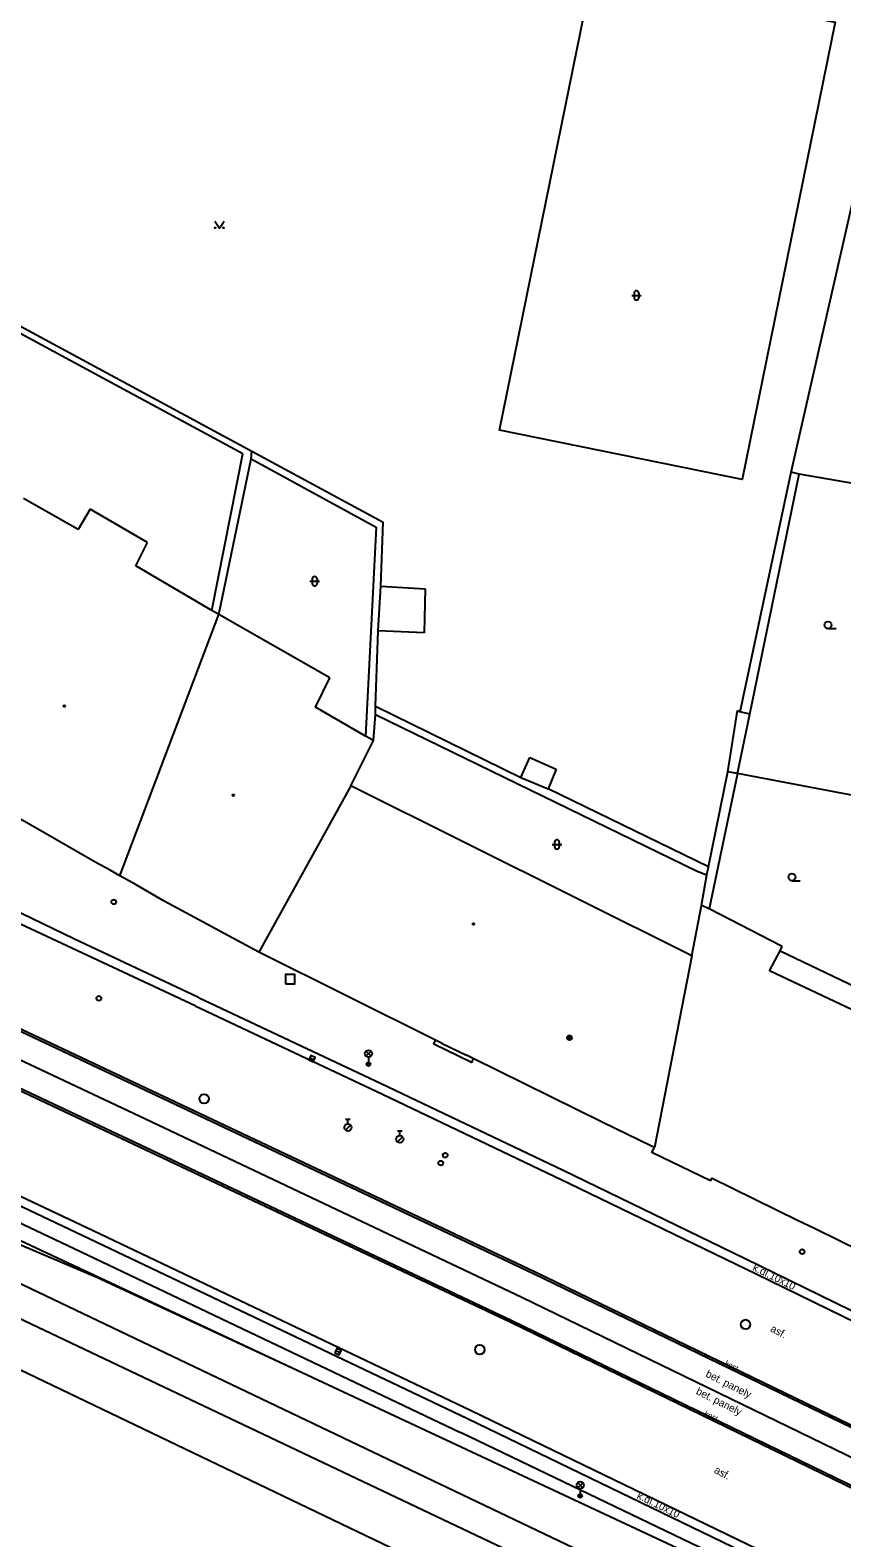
# Model space of a CAD drawing. Extents: x -599770 to -598493, y -1162076 to -1159209.
# Drawn here: x -599061.2 to -599018.2, y -1161643.6 to -1161563.7 of the extents above; entities that cross this region are included whole.
import ezdxf

# ---------------------------------------------------------------- set-up
doc = ezdxf.new("R2010")
doc.units = 0
doc.layers.add('Podklad', color=7, linetype='Continuous')

msp = doc.modelspace()

# ---------------------------------------------------------------- linework, layer by layer
at = {"layer": 'Podklad'}
for p, q in [((-599029.343, -1161577.778), (-599028.843, -1161577.778)), ((-599029.218, -1161577.653), (-599029.218, -1161577.903)), ((-599028.968, -1161577.653), (-599028.968, -1161577.903)), ((-599046.393, -1161592.918), (-599045.893, -1161592.918)), ((-599046.268, -1161592.793), (-599046.268, -1161593.043)), ((-599046.018, -1161592.793), (-599046.018, -1161593.043)), ((-599018.94, -1161595.427), (-599018.503, -1161595.427)), ((-599033.553, -1161606.858), (-599033.053, -1161606.858)), ((-599033.428, -1161606.733), (-599033.428, -1161606.983)), ((-599033.178, -1161606.733), (-599033.178, -1161606.983)), ((-599020.85, -1161608.777), (-599020.413, -1161608.777)), ((-599043.422, -1161618.07), (-599043.157, -1161617.805)), ((-599043.422, -1161617.805), (-599043.157, -1161618.07)), ((-599046.394, -1161618.159), (-599046.166, -1161618.261)), ((-599043.29, -1161618.125), (-599043.29, -1161618.5)), ((-599044.509, -1161621.986), (-599044.244, -1161621.721)), ((-599044.505, -1161621.413), (-599044.255, -1161621.413)), ((-599044.38, -1161621.663), (-599044.38, -1161621.413)), ((-599041.759, -1161622.606), (-599041.494, -1161622.341)), ((-599041.755, -1161622.032), (-599041.505, -1161622.032)), ((-599041.63, -1161622.282), (-599041.63, -1161622.032)), ((-599045.014, -1161633.669), (-599044.786, -1161633.771)), ((-599032.203, -1161640.93), (-599031.938, -1161640.665)), ((-599032.203, -1161640.665), (-599031.938, -1161640.93)), ((-599032.07, -1161640.985), (-599032.07, -1161641.36))]:
    msp.add_line(p, q, dxfattribs=at)
for points in [[(-599031.42, -1161560.68), (-599018.56, -1161563.3), (-599023.49, -1161587.53), (-599036.35, -1161584.91), (-599031.42, -1161560.68)], [(-599020.9, -1161587.14), (-599017.25, -1161571.16)], [(-599051.44, -1161573.845), (-599051.19, -1161574.22), (-599050.94, -1161573.845)], [(-599062.19, -1161579.16), (-599049.47, -1161586.03)], [(-599049.95, -1161586.17), (-599061.95, -1161579.68)], [(-599046.81, -1161634.84), (-599057.69, -1161629.79), (-599077.21, -1161621.52), (-599107.62, -1161606.51), (-599123.82, -1161598.98), (-599130.01, -1161596.49), (-599139.8, -1161592.75), (-599147.32, -1161590.34), (-599156.02, -1161588.13), (-599168.93, -1161585.63), (-599175.32, -1161584.75), (-599179.38, -1161584.08), (-599180.25, -1161583.92)], [(-599180.25, -1161583.92), (-599163, -1161589.64), (-599143.65, -1161594.17), (-599135.02, -1161596.97), (-599114.73, -1161605.82), (-599080.75, -1161621.2), (-599065.94, -1161628.12), (-598998.09, -1161660.51), (-598974.99, -1161672.34), (-598953.07, -1161685.05), (-598929.76, -1161698.95), (-598888.91, -1161727.38), (-598861.19, -1161748.52), (-598845.68, -1161761.08), (-598825.16, -1161781.28), (-598808.06, -1161799.42), (-598788.14, -1161822.37), (-598730.99, -1161888.48), (-598729.85, -1161889.88)], [(-599180.25, -1161583.92), (-599163, -1161589.64), (-599143.65, -1161594.17), (-599135.02, -1161596.97), (-599114.73, -1161605.82), (-599080.75, -1161621.2), (-599065.94, -1161628.12), (-598998.09, -1161660.51), (-598974.99, -1161672.34), (-598953.07, -1161685.05), (-598929.76, -1161698.95), (-598888.91, -1161727.38), (-598861.19, -1161748.52), (-598845.68, -1161761.08), (-598825.16, -1161781.28), (-598808.06, -1161799.42), (-598788.14, -1161822.37), (-598730.99, -1161888.48), (-598729.85, -1161889.88)], [(-598799.44, -1161805.85), (-598802.25, -1161802.78), (-598809.5, -1161794.72), (-598819.13, -1161784.01), (-598839.67, -1161763.81), (-598854.43, -1161750.62), (-598875.37, -1161733.68), (-598894.03, -1161720.2), (-598928.44, -1161696.82), (-598960.02, -1161677.8), (-598988.42, -1161662.64), (-599021.49, -1161646.68), (-599046.81, -1161634.84), (-599071.35, -1161623.36), (-599123.82, -1161598.98), (-599139.8, -1161592.75), (-599147.26, -1161591.17), (-599155.59, -1161588.64), (-599172.59, -1161585.56), (-599172.49, -1161585.13)], [(-599051.59, -1161594.47), (-599049.95, -1161586.17)], [(-599051.22, -1161594.68), (-599049.51, -1161586.43)], [(-599049.51, -1161586.43), (-599049.47, -1161586.03)], [(-599049.51, -1161586.43), (-599042.89, -1161590.06)], [(-599049.47, -1161586.03), (-599042.52, -1161589.78)], [(-599023.59, -1161599.84), (-599020.9, -1161587.14)], [(-599023.09, -1161599.95), (-599020.47, -1161587.24)], [(-599020.47, -1161587.24), (-599020.9, -1161587.14)], [(-599006.55, -1161589.65), (-599020.47, -1161587.24)], [(-599058.68, -1161590.17), (-599061.57, -1161588.54)], [(-599058.04, -1161589.09), (-599058.68, -1161590.17)], [(-599055, -1161590.87), (-599058.04, -1161589.09)], [(-599042.63, -1161593.18), (-599042.52, -1161589.78)], [(-599042.89, -1161590.06), (-599043.44, -1161601.12)], [(-599115.96, -1161591.25), (-599095.12, -1161600.92), (-599074.43, -1161610.64), (-599054.45, -1161620.05), (-599034.5, -1161629.48), (-599014.88, -1161638.97)], [(-599055.62, -1161592.1), (-599055, -1161590.87)], [(-599051.59, -1161594.47), (-599055.62, -1161592.1)], [(-599116.59, -1161592.61), (-599095.76, -1161602.26), (-599075.07, -1161612), (-599055.11, -1161621.39), (-599035.17, -1161630.84), (-599015.52, -1161640.38)], [(-598930.62, -1161703.45), (-598962.96, -1161683.9), (-598992.16, -1161668.11), (-599026.86, -1161651.42), (-599073.57, -1161629.03), (-599101.81, -1161615.97), (-599128.28, -1161604.09), (-599151.72, -1161596.53), (-599162, -1161593.26)], [(-599117.17, -1161593.85), (-599096.33, -1161603.54), (-599075.6, -1161613.25), (-599055.71, -1161622.61), (-599035.69, -1161632.07), (-599016.08, -1161641.59)], [(-599042.77, -1161595.54), (-599042.63, -1161593.18)], [(-599042.63, -1161593.18), (-599040.29, -1161593.32)], [(-599040.29, -1161593.32), (-599040.34, -1161595.65)], [(-599117.2, -1161593.96), (-599096.38, -1161603.64), (-599075.65, -1161613.35), (-599055.76, -1161622.71), (-599035.74, -1161632.17)], [(-599056.47, -1161608.52), (-599051.22, -1161594.68)], [(-599051.22, -1161594.68), (-599051.59, -1161594.47)], [(-599045.34, -1161598.03), (-599051.22, -1161594.68)], [(-599052.47, -1161615.41), (-599062.53, -1161610.71), (-599072.48, -1161605.78), (-599082.32, -1161600.61), (-599092.03, -1161595.22)], [(-599042.92, -1161599.54), (-599042.77, -1161595.54)], [(-599040.34, -1161595.65), (-599042.77, -1161595.54)], [(-599119.41, -1161598.56), (-599098.38, -1161608.27), (-599077.78, -1161617.91), (-599057.88, -1161627.31), (-599037.85, -1161636.84), (-599018.34, -1161646.27), (-599000.52, -1161655.17), (-598981.12, -1161665.1)], [(-599046.09, -1161599.58), (-599045.34, -1161598.03)], [(-599119.94, -1161599.72), (-599098.94, -1161609.4), (-599078.3, -1161619.08), (-599058.56, -1161628.42), (-599038.42, -1161638)], [(-599043.44, -1161601.12), (-599046.09, -1161599.58)], [(-599043.03, -1161601.36), (-599042.92, -1161599.98)], [(-599042.92, -1161599.54), (-599035.21, -1161603.31)], [(-599042.92, -1161599.98), (-599042.92, -1161599.54)], [(-599042.92, -1161599.98), (-599025.87, -1161608.28)], [(-599024.25, -1161603.01), (-599023.73, -1161599.77)], [(-599023.74, -1161603.1), (-599023.09, -1161599.95)], [(-599023.73, -1161599.77), (-599023.59, -1161599.84)], [(-599023.09, -1161599.95), (-599023.59, -1161599.84)], [(-599095.17, -1161601.02), (-599074.48, -1161610.74), (-599054.5, -1161620.15), (-599034.55, -1161629.58), (-599014.93, -1161639.07)], [(-599044.23, -1161603.75), (-599043.03, -1161601.36)], [(-599043.03, -1161601.36), (-599043.44, -1161601.12)], [(-599035.21, -1161603.31), (-599034.74, -1161602.25)], [(-599034.74, -1161602.25), (-599033.34, -1161602.87)], [(-599035.21, -1161603.31), (-599033.76, -1161603.92)], [(-599033.34, -1161602.87), (-599033.76, -1161603.92)], [(-599025.27, -1161608.04), (-599024.25, -1161603.01)], [(-599023.74, -1161603.1), (-599025.23, -1161610.27)], [(-599023.74, -1161603.1), (-599024.25, -1161603.01)], [(-599010.81, -1161605.55), (-599023.74, -1161603.1)], [(-599044.23, -1161603.75), (-599049.1, -1161612.57)], [(-599026.15, -1161612.76), (-599044.23, -1161603.75)], [(-599025.27, -1161608.04), (-599033.76, -1161603.92)], [(-599052.29, -1161614.97), (-599058.9, -1161611.85), (-599065.49, -1161608.68), (-599072.06, -1161605.46)], [(-599060.87, -1161606.01), (-599062.39, -1161605.15)], [(-599057.74, -1161607.81), (-599060.87, -1161606.01)], [(-599056.98, -1161608.22), (-599057.74, -1161607.81)], [(-599056.47, -1161608.52), (-599056.98, -1161608.22)], [(-599025.87, -1161608.28), (-599025.36, -1161608.47)], [(-599025.36, -1161608.47), (-599025.27, -1161608.04)], [(-599055.61, -1161609), (-599056.47, -1161608.52)], [(-599054.11, -1161609.86), (-599055.61, -1161609)], [(-599025.64, -1161610.1), (-599025.36, -1161608.47)], [(-599039.38, -1161617.4), (-599039.74, -1161617.22), (-599049.1, -1161612.57), (-599054.11, -1161609.86)], [(-599026.15, -1161612.76), (-599025.64, -1161610.1)], [(-599025.23, -1161610.27), (-599025.64, -1161610.1)], [(-599021.36, -1161612.26), (-599025.23, -1161610.27)], [(-599021.48, -1161612.49), (-599021.36, -1161612.26)], [(-599026.15, -1161612.76), (-599028.14, -1161622.91)], [(-599022.04, -1161613.55), (-599021.48, -1161612.49)], [(-599021.48, -1161612.49), (-599014.26, -1161615.93)], [(-599014.25, -1161617.23), (-599022.04, -1161613.55)], [(-599052.47, -1161615.41), (-599042.54, -1161620.09), (-599032.63, -1161624.82), (-599022.74, -1161629.6), (-599012.88, -1161634.43)], [(-599052.29, -1161614.97), (-599042.62, -1161619.52), (-599032.98, -1161624.12), (-599023.36, -1161628.77), (-599013.76, -1161633.47)], [(-599037.74, -1161618.2), (-599037.84, -1161618.41), (-599039.82, -1161617.44), (-599039.74, -1161617.22)], [(-599039.38, -1161617.4), (-599038.1, -1161618.02)], [(-599077.94, -1161618.34), (-599077.99, -1161618.46), (-599077.56, -1161618.66), (-599077.49, -1161618.54), (-599058.09, -1161627.73), (-599038.04, -1161637.26), (-599018.57, -1161646.67), (-599000.7, -1161655.58), (-598987.87, -1161662.14)], [(-599037.74, -1161618.2), (-599038.1, -1161618.02)], [(-599028.32, -1161622.82), (-599030.88, -1161621.58), (-599037.74, -1161618.2)], [(-599028.14, -1161622.91), (-599028.32, -1161622.82)], [(-599025.17, -1161624.67), (-599028.27, -1161623.18), (-599028.14, -1161622.91)], [(-599025.11, -1161624.53), (-599025.17, -1161624.67)], [(-599020.56, -1161626.77), (-599025.11, -1161624.53)], [(-599019.65, -1161627.21), (-599020.56, -1161626.77)], [(-599010.98, -1161631.48), (-599019.65, -1161627.21)], [(-598997.49, -1161662.49), (-599067.18, -1161629.42)], [(-599035.74, -1161632.17), (-599016.13, -1161641.69)], [(-598854.43, -1161750.62), (-598878.6, -1161731.32), (-598890.77, -1161722.52), (-598916.28, -1161704.63), (-598934.68, -1161692.84), (-598949.07, -1161684.29), (-598960.02, -1161677.8), (-598968.53, -1161673.05), (-598983.84, -1161664.94), (-598998.49, -1161657.68), (-599021.49, -1161646.68), (-599046.81, -1161634.84)], [(-599018.93, -1161647.36), (-599038.42, -1161638)]]:
    msp.add_lwpolyline(points, dxfattribs=at)
for points in [[(-599047.69, -1161614.25), (-599047.19, -1161614.25), (-599047.19, -1161613.75), (-599047.69, -1161613.75)], [(-599046.445, -1161618.273), (-599046.217, -1161618.375), (-599046.115, -1161618.147), (-599046.343, -1161618.045)], [(-599045.065, -1161633.783), (-599044.837, -1161633.885), (-599044.735, -1161633.657), (-599044.963, -1161633.555)]]:
    msp.add_lwpolyline(points, close=True, dxfattribs=at)
for centre, radius in [((-599051.415, -1161574.195), 0.025), ((-599050.965, -1161574.195), 0.025), ((-599018.94, -1161595.24), 0.188), ((-599059.41, -1161599.53), 0.045), ((-599059.41, -1161599.53), 0.0199), ((-599050.45, -1161604.25), 0.045), ((-599050.45, -1161604.25), 0.0199), ((-599020.85, -1161608.59), 0.188), ((-599056.79, -1161609.9), 0.125), ((-599037.73, -1161611.07), 0.045), ((-599037.73, -1161611.07), 0.0199), ((-599057.58, -1161615.01), 0.125), ((-599032.64, -1161617.1), 0.125), ((-599032.64, -1161617.1), 0.1), ((-599032.64, -1161617.1), 0.075), ((-599032.64, -1161617.1), 0.05), ((-599043.29, -1161617.938), 0.188), ((-599032.64, -1161617.1), 0.025), ((-599043.29, -1161618.5), 0.1), ((-599043.29, -1161618.5), 0.0723), ((-599043.29, -1161618.5), 0.0438), ((-599052, -1161620.33), 0.25), ((-599044.38, -1161621.85), 0.188), ((-599041.63, -1161622.47), 0.188), ((-599039.22, -1161623.32), 0.125), ((-599039.46, -1161623.74), 0.125), ((-599020.31, -1161628.43), 0.125), ((-599023.31, -1161632.28), 0.25), ((-599037.39, -1161633.62), 0.25), ((-599032.07, -1161640.797), 0.188), ((-599032.07, -1161641.36), 0.1), ((-599032.07, -1161641.36), 0.0723), ((-599032.07, -1161641.36), 0.0438)]:
    msp.add_circle(centre, radius, dxfattribs=at)
for centre, start, end in [((-599029.093, -1161577.653), 0, 180), ((-599029.093, -1161577.903), 180, 0), ((-599046.143, -1161592.793), 0, 180), ((-599046.143, -1161593.043), 180, 0), ((-599033.303, -1161606.733), 0, 180), ((-599033.303, -1161606.983), 180, 0)]:
    msp.add_arc(centre, 0.125, start, end, dxfattribs=at)

# ---------------------------------------------------------------- texts
for s, height, rotation, p in [('k.dl.10x10', 0.4, 333.75202, (-599022.97, -1161629.4)), ('asf.', 0.4, 332.08728, (-599022.03, -1161632.63)), ('kost.', 0.3, 333.32358, (-599024.44, -1161634.44)), ('bet. panely', 0.4, 333.41678, (-599025.46, -1161635.03)), ('bet. panely', 0.4, 333.41678, (-599025.97, -1161635.95)), ('kost.', 0.3, 333.32358, (-599025.52, -1161637.1)), ('asf.', 0.4, 332.08728, (-599025.01, -1161640.12)), ('k.dl.10x10', 0.4, 333.75202, (-599029.1, -1161641.48))]:
    msp.add_text(s, height=height, rotation=rotation, dxfattribs=at).set_placement(p)

doc.saveas('drawing.dxf')
